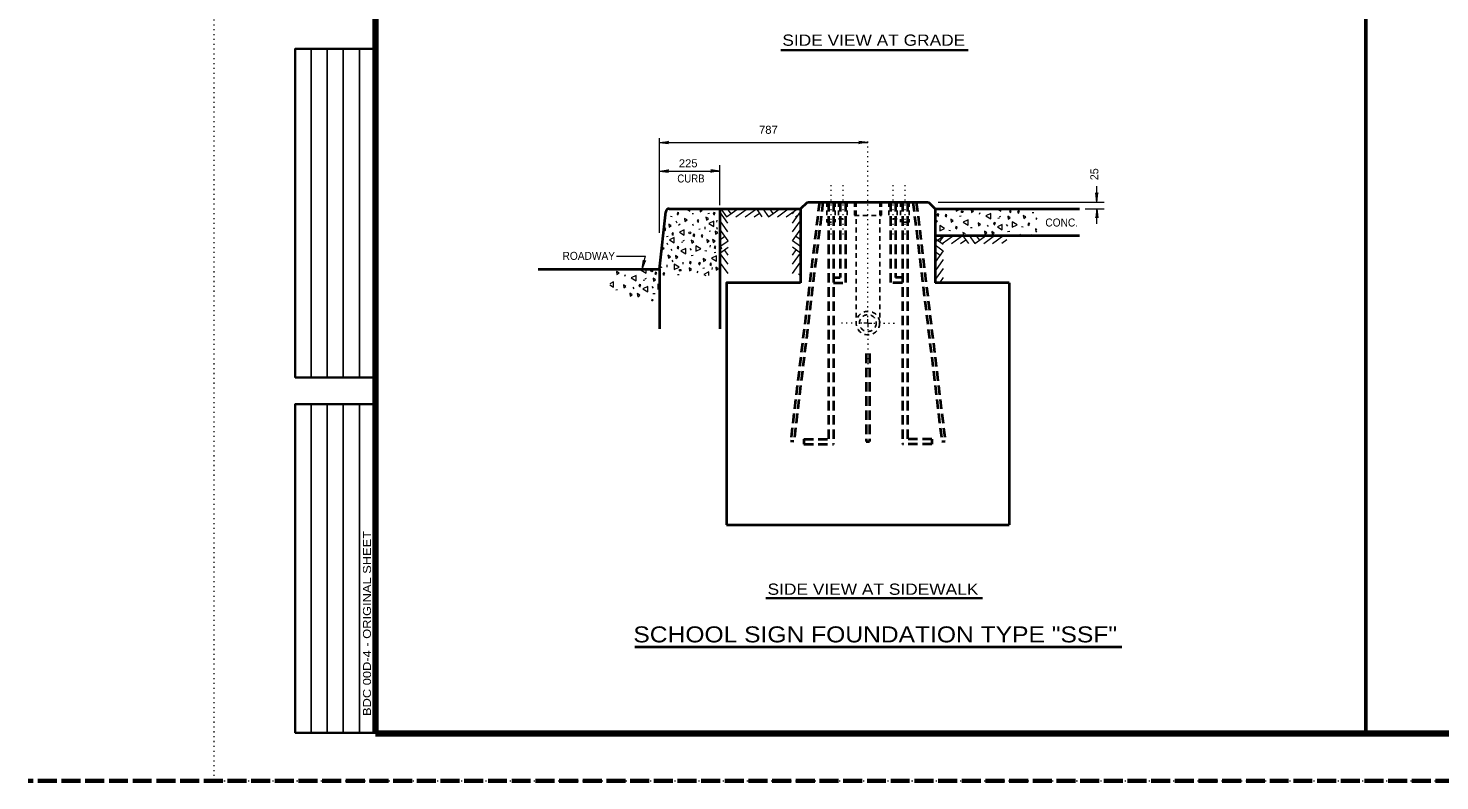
# Model space of a CAD drawing. Extents: x 312583 to 312854, y 144419 to 144597.
# Drawn here: x 312583.5 to 312717.6, y 144418.6 to 144490.1 of the extents above; entities that cross this region are included whole.
import ezdxf
from ezdxf.enums import TextEntityAlignment as Align

# ---------------------------------------------------------------- set-up
doc = ezdxf.new("R2010")
doc.units = 0
doc.header["$LTSCALE"] = 0.3
for name, pattern in [('DOTTED', [1.5, 0.3, -1.2]), ('LONG_DASHED', [7.5, 6, -1.5]), ('MEDIUM_DASHED', [4.5, 3, -1.5]), ('SHORT_DASHED', [2.7, 1.5, -1.2])]:
    doc.linetypes.add(name, pattern=pattern)
for name, color, linetype, lineweight in [('1', 7, 'Continuous', 40), ('2', 7, 'Continuous', 13), ('62', 7, 'DOTTED', 13), ('63', 7, 'LONG_DASHED', 60)]:
    doc.layers.add(name, color=color, linetype=linetype, lineweight=lineweight)

msp = doc.modelspace()

# ---------------------------------------------------------------- linework, layer by layer
at = {"layer": '1', "lineweight": 53}
msp.add_line((312710.5662, 144423.0846), (312710.5662, 144585.0846), dxfattribs=at)
at = {"layer": '1', "lineweight": 25}
for p, q in [((312610.4087, 144456.901), (312610.4087, 144488.1192)), ((312611.9315, 144456.901), (312611.9315, 144488.1192)), ((312613.4543, 144456.901), (312613.4543, 144488.1192)), ((312614.9772, 144456.901), (312614.9772, 144488.1192)), ((312610.4087, 144423.1446), (312610.4087, 144454.3629)), ((312611.9315, 144423.1446), (312611.9315, 144454.3629)), ((312613.4543, 144423.1446), (312613.4543, 144454.3629)), ((312614.9772, 144423.1446), (312614.9772, 144454.3629))]:
    msp.add_line(p, q, dxfattribs=at)
at = {"layer": '1', "linetype": 'DOTTED', "lineweight": 13}
for p, q in [((312659.772, 144475.1823), (312659.772, 144470.383)), ((312660.9066, 144475.1823), (312660.9066, 144470.383)), ((312665.66, 144475.1823), (312665.66, 144470.383)), ((312666.7946, 144475.1823), (312666.7946, 144470.383))]:
    msp.add_line(p, q, dxfattribs=at)
at = {"layer": '1'}
for p, q in [((312644.4003, 144472.9283), (312656.897, 144472.9283)), ((312649.2303, 144472.9283), (312649.2303, 144461.5127)), ((312656.897, 144472.9283), (312657.5333, 144473.5647)), ((312656.897, 144472.9283), (312656.897, 144465.898)), ((312657.5333, 144473.5647), (312669.0333, 144473.5647)), ((312669.0333, 144473.5647), (312669.6696, 144472.9283)), ((312669.6696, 144472.9283), (312669.6696, 144465.898)), ((312669.6696, 144472.9283), (312683.3853, 144472.9283)), ((312669.6696, 144470.3753), (312683.3853, 144470.3753)), ((312643.4803, 144467.1783), (312643.4803, 144461.5127)), ((312676.7, 144465.898), (312669.6696, 144465.898)), ((312676.7, 144465.898), (312676.7, 144442.898)), ((312649.8666, 144442.898), (312676.7, 144442.898))]:
    msp.add_line(p, q, dxfattribs=at)
at = {"layer": '1', "lineweight": 13}
for p, q in [((312645.9413, 144472.959), (312646.3553, 144472.706)), ((312646.3553, 144472.706), (312646.3553, 144472.959)), ((312649.9203, 144472.913), (312650.2576, 144472.453)), ((312650.549, 144472.913), (312650.6716, 144472.7443)), ((312650.733, 144472.1693), (312651.8063, 144472.9283)), ((312651.6146, 144472.1693), (312652.688, 144472.9283)), ((312652.688, 144472.9283), (312653.2246, 144472.1693)), ((312653.309, 144472.9283), (312653.8533, 144472.1693)), ((312653.8533, 144472.1693), (312654.942, 144472.936)), ((312653.9376, 144472.9283), (312654.2673, 144472.4607)), ((312654.5663, 144472.9283), (312654.689, 144472.7597)), ((312654.689, 144472.1693), (312655.724, 144472.9053)), ((312655.5323, 144472.1693), (312656.598, 144472.9283)), ((312656.1303, 144472.4453), (312656.4753, 144472.9283)), ((312670.398, 144472.9053), (312670.5436, 144472.9437)), ((312670.973, 144472.959), (312670.9806, 144472.9283)), ((312675.4656, 144472.959), (312675.9026, 144472.6983)), ((312675.9026, 144472.6983), (312675.9026, 144472.959)), ((312644.5306, 144472.2307), (312644.6993, 144472.1847)), ((312645.052, 144471.7707), (312645.1363, 144471.602)), ((312645.466, 144471.4563), (312645.282, 144471.326)), ((312646.5776, 144472.476), (312646.7233, 144472.4837)), ((312646.616, 144471.4947), (312646.7003, 144471.326)), ((312648.088, 144472.4607), (312648.2336, 144472.4913)), ((312648.939, 144471.6403), (312648.962, 144471.832)), ((312649.9893, 144471.5637), (312649.2303, 144472.6293)), ((312649.9893, 144470.7203), (312649.2533, 144471.763)), ((312652.4963, 144472.1693), (312652.9793, 144472.5143)), ((312656.1303, 144471.5637), (312656.897, 144472.6293)), ((312656.1303, 144470.7203), (312656.874, 144471.763)), ((312656.4063, 144472.1693), (312656.897, 144472.5143)), ((312672.0003, 144472.2307), (312672.146, 144472.2383)), ((312673.9093, 144472.5527), (312673.8403, 144472.384)), ((312675.6266, 144472.0237), (312675.7723, 144472.0543)), ((312675.7953, 144472.154), (312675.9256, 144472.223)), ((312678.8926, 144472.5757), (312679.0383, 144472.5833)), ((312644.1626, 144470.291), (312644.3083, 144470.3217)), ((312647.2216, 144470.9733), (312647.3673, 144471.0117)), ((312647.7813, 144471.2033), (312647.8043, 144470.9963)), ((312648.1953, 144470.7893), (312648.341, 144470.82)), ((312648.893, 144471.1727), (312648.9773, 144470.9963)), ((312649.997, 144469.8923), (312649.215, 144470.9733)), ((312649.2303, 144470.5977), (312649.399, 144470.7203)), ((312649.2303, 144469.9767), (312649.698, 144470.3063)), ((312656.1303, 144469.8923), (312656.9046, 144470.9733)), ((312656.8893, 144469.9767), (312656.4216, 144470.3063)), ((312656.8893, 144470.5977), (312656.7206, 144470.7203)), ((312669.6696, 144469.7697), (312670.5206, 144470.3753)), ((312669.6696, 144470.1453), (312669.8536, 144469.9)), ((312669.6696, 144470.107), (312670.4363, 144469.5703)), ((312670.4363, 144470.2987), (312670.0913, 144469.8157)), ((312670.145, 144470.36), (312670.2676, 144470.199)), ((312670.3366, 144469.6163), (312671.4023, 144470.383)), ((312670.973, 144470.889), (312671.1416, 144470.8507)), ((312671.2183, 144469.6163), (312672.2763, 144470.3907)), ((312672.2763, 144470.3907), (312672.8283, 144469.6317)), ((312672.905, 144470.3907), (312673.457, 144469.6317)), ((312673.02, 144471.1343), (312673.1733, 144471.142)), ((312673.457, 144469.6317), (312674.538, 144470.4137)), ((312673.5336, 144470.3983), (312673.871, 144469.9307)), ((312674.1623, 144470.3983), (312674.285, 144470.2297)), ((312674.285, 144469.6393), (312675.32, 144470.383)), ((312674.6223, 144471.3643), (312674.722, 144471.2263)), ((312675.1283, 144469.6393), (312676.194, 144470.4137)), ((312676.4316, 144471.4257), (312676.5543, 144471.2723)), ((312676.5466, 144470.774), (312676.7613, 144470.7817)), ((312677.8653, 144471.234), (312678.034, 144471.1957)), ((312678.8006, 144470.4597), (312678.7163, 144470.406)), ((312679.2453, 144470.728), (312679.3373, 144470.7893)), ((312644.1703, 144469.6853), (312644.2623, 144469.5167)), ((312644.5613, 144469.0873), (312644.661, 144468.9493)), ((312645.5656, 144469.7467), (312645.7113, 144469.7773)), ((312645.7343, 144469.877), (312645.8646, 144469.946)), ((312646.3706, 144469.1487), (312646.4933, 144468.9877)), ((312647.8043, 144468.957), (312647.973, 144468.9187)), ((312648.3103, 144469.2867), (312648.3333, 144469.4707)), ((312648.6936, 144468.7577), (312648.8393, 144468.7883)), ((312649.2303, 144469.348), (312649.997, 144469.8923)), ((312649.2303, 144468.7193), (312649.997, 144469.2637)), ((312649.997, 144468.5277), (312649.652, 144469.0183)), ((312656.8893, 144468.7193), (312656.1226, 144469.2637)), ((312656.1226, 144468.5277), (312656.4753, 144469.0183)), ((312656.8893, 144469.348), (312656.1303, 144469.8923)), ((312670.4363, 144468.9417), (312669.662, 144467.853)), ((312669.6696, 144469.486), (312670.4363, 144468.9417)), ((312669.6696, 144468.8573), (312670.1373, 144468.52)), ((312672.0923, 144469.624), (312672.583, 144469.9767)), ((312676.01, 144469.647), (312676.493, 144469.9997)), ((312644.1703, 144467.5923), (312644.1933, 144467.3777)), ((312644.6686, 144468.037), (312644.753, 144467.8683)), ((312645.7266, 144467.6613), (312645.7496, 144467.853)), ((312646.4856, 144468.497), (312646.7003, 144468.5047)), ((312649.997, 144467.6537), (312649.2303, 144468.7193)), ((312649.997, 144466.772), (312649.2303, 144467.8377)), ((312656.1226, 144467.6537), (312656.8893, 144468.7193)), ((312656.1226, 144466.772), (312656.8816, 144467.8377)), ((312669.6696, 144468.2287), (312669.8383, 144468.106)), ((312670.4363, 144468.106), (312669.6926, 144467.071)), ((312640.2373, 144466.657), (312640.1606, 144466.4883)), ((312641.947, 144466.128), (312642.0926, 144466.1587)), ((312642.1156, 144466.2583), (312642.246, 144466.335)), ((312642.223, 144466.8027), (312642.223, 144467.209)), ((312643.603, 144467.3547), (312643.7486, 144467.393)), ((312645.213, 144466.68), (312645.3586, 144466.6877)), ((312647.122, 144467.002), (312647.0453, 144466.8333)), ((312647.6203, 144467.278), (312647.766, 144467.301)), ((312648.502, 144467.14), (312648.525, 144467.3317)), ((312656.874, 144466.588), (312656.7053, 144466.703)), ((312670.4363, 144467.2627), (312669.6696, 144466.197)), ((312670.4363, 144466.3887), (312670.0913, 144465.898)), ((312638.7653, 144465.691), (312639.1256, 144465.4763)), ((312639.3403, 144465.2387), (312639.4936, 144465.254)), ((312640.9426, 144465.4763), (312641.05, 144465.3307)), ((312642.752, 144465.53), (312642.8746, 144465.3767)), ((312642.867, 144464.8783), (312643.0816, 144464.886)), ((312643.3346, 144465.783), (312643.3193, 144465.7907)), ((312642.8363, 144464.1577), (312642.8363, 144464.1807))]:
    msp.add_line(p, q, dxfattribs=at)
at = {"layer": '1', "linetype": 'MEDIUM_DASHED'}
for p, q in [((312658.6833, 144473.5647), (312655.9386, 144450.8483)), ((312659.0053, 144473.5647), (312656.253, 144450.81)), ((312659.5266, 144473.5647), (312659.5266, 144451.0477)), ((312660.0096, 144473.5647), (312660.0096, 144450.5647)), ((312660.6613, 144473.5647), (312660.6613, 144466.381)), ((312661.1443, 144473.5647), (312661.1443, 144465.898)), ((312665.4223, 144473.5647), (312665.4223, 144465.898)), ((312665.9053, 144473.5647), (312665.9053, 144466.381)), ((312666.557, 144473.5647), (312666.557, 144450.5647)), ((312667.04, 144473.5647), (312667.04, 144451.0477)), ((312667.5613, 144473.5647), (312670.3136, 144450.81)), ((312667.8833, 144473.5647), (312670.628, 144450.8483)), ((312660.0096, 144466.381), (312660.6613, 144466.381)), ((312666.557, 144466.381), (312665.9053, 144466.381)), ((312660.0096, 144465.898), (312661.1443, 144465.898)), ((312666.557, 144465.898), (312665.4223, 144465.898)), ((312663.1223, 144459.1667), (312663.1223, 144450.81)), ((312663.4443, 144459.1667), (312663.4443, 144450.81)), ((312656.253, 144450.81), (312655.9386, 144450.8483)), ((312657.2113, 144451.0477), (312659.5266, 144451.0477)), ((312657.2113, 144451.0477), (312657.2113, 144450.5647)), ((312657.2113, 144450.5647), (312660.002, 144450.5647)), ((312663.1223, 144450.81), (312663.4443, 144450.81)), ((312669.3553, 144450.5647), (312666.5646, 144450.5647)), ((312669.3553, 144451.0477), (312667.04, 144451.0477)), ((312669.3553, 144451.0477), (312669.3553, 144450.5647)), ((312670.3136, 144450.81), (312670.628, 144450.8483))]:
    msp.add_line(p, q, dxfattribs=at)
at = {"layer": '1', "linetype": 'SHORT_DASHED', "lineweight": 25}
for p, q in [((312659.3733, 144473.5647), (312659.3733, 144471.648)), ((312660.1706, 144473.5647), (312660.1706, 144471.648)), ((312660.5003, 144473.5647), (312660.5003, 144471.97)), ((312661.3053, 144473.5647), (312661.3053, 144471.97)), ((312662.164, 144473.5647), (312662.164, 144462.0647)), ((312664.4026, 144473.5647), (312664.4026, 144462.0647)), ((312664.5636, 144473.5647), (312664.5636, 144472.292)), ((312665.2613, 144473.5647), (312665.2613, 144471.97)), ((312666.0586, 144473.5647), (312666.0586, 144471.97)), ((312666.396, 144473.5647), (312666.396, 144471.648)), ((312667.1933, 144473.5647), (312667.1933, 144471.648)), ((312659.3733, 144471.648), (312660.1706, 144471.648)), ((312660.5003, 144471.97), (312661.3053, 144471.97)), ((312666.0586, 144471.97), (312665.2613, 144471.97)), ((312667.1933, 144471.648), (312666.396, 144471.648))]:
    msp.add_line(p, q, dxfattribs=at)
at = {"layer": '1', "lineweight": 158}
msp.add_line((312616.5, 144423.0846), (312849, 144423.0846), dxfattribs=at)
msp.add_lwpolyline([(312616.5, 144423.1446), (312616.5, 144585.0846), (312849, 144585.0846)], dxfattribs=at)
at = {"layer": '1', "lineweight": 35}
for points in [[(312616.5, 144456.901), (312608.8858, 144456.901), (312608.8858, 144488.1192), (312616.5, 144488.1192)], [(312616.5, 144423.1446), (312608.8858, 144423.1446), (312608.8858, 144454.3629), (312616.5, 144454.3629)]]:
    msp.add_lwpolyline(points, dxfattribs=at)
at = {"layer": '1', "lineweight": 13}
for points in [[(312647.352, 144472.6447), (312647.5436, 144472.7903), (312647.3136, 144472.9283)], [(312673.1273, 144472.568), (312673.3266, 144472.7137), (312673.089, 144472.8517)], [(312644.408, 144471.1803), (312644.6073, 144471.326), (312644.3696, 144471.464)], [(312645.2743, 144472.453), (312645.3203, 144472.5297), (312645.2053, 144472.568), (312645.1516, 144472.4147), (312645.2743, 144472.3457)], [(312645.9106, 144471.717), (312646.11, 144471.8703), (312645.8723, 144472.0083)], [(312647.1833, 144471.763), (312647.2293, 144471.8397), (312647.1143, 144471.878), (312647.053, 144471.7247), (312647.1833, 144471.6557)], [(312647.95, 144471.8473), (312648.1416, 144471.993), (312647.904, 144472.1387)], [(312648.6476, 144471.234), (312648.6476, 144471.7477), (312648.18, 144471.51)], [(312648.7166, 144472.4453), (312648.7703, 144472.5297), (312648.6476, 144472.568), (312648.594, 144472.4147), (312648.7166, 144472.3457)], [(312669.9763, 144472.3227), (312670.0223, 144472.3993), (312669.9073, 144472.4377), (312669.846, 144472.2843), (312669.9763, 144472.2153)], [(312670.7353, 144472.269), (312670.789, 144472.3533), (312670.6663, 144472.384), (312670.6126, 144472.2307), (312670.7353, 144472.1617)], [(312671.1953, 144471.6633), (312671.387, 144471.809), (312671.157, 144471.947)], [(312672.8053, 144471.3643), (312672.8053, 144471.8857), (312672.3376, 144471.648)], [(312673.7943, 144471.303), (312673.986, 144471.4487), (312673.756, 144471.5867)], [(312674.952, 144471.9623), (312674.952, 144472.476), (312674.4843, 144472.246)], [(312675.343, 144471.4947), (312675.389, 144471.579), (312675.274, 144471.6173), (312675.2126, 144471.464), (312675.343, 144471.395)], [(312676.608, 144471.9317), (312676.7996, 144472.0773), (312676.562, 144472.2153)], [(312676.861, 144472.6677), (312676.907, 144472.7443), (312676.792, 144472.7827), (312676.7383, 144472.6293), (312676.861, 144472.5603)], [(312676.999, 144471.6863), (312676.999, 144471.1727), (312677.4666, 144471.4027)], [(312677.6276, 144472.614), (312677.6736, 144472.6907), (312677.5586, 144472.729), (312677.4973, 144472.5757), (312677.6276, 144472.5067)], [(312678.0876, 144472.0083), (312678.2793, 144472.154), (312678.0416, 144472.292)], [(312678.609, 144471.4563), (312678.655, 144471.5407), (312678.54, 144471.5713), (312678.4863, 144471.418), (312678.609, 144471.349)], [(312644.891, 144469.6853), (312644.891, 144470.199), (312644.4233, 144469.969)], [(312644.7836, 144470.5133), (312644.8296, 144470.5977), (312644.7146, 144470.636), (312644.6533, 144470.4827), (312644.7836, 144470.4137)], [(312645.834, 144470.4213), (312645.834, 144470.935), (312645.374, 144470.705)], [(312646.8, 144470.3907), (312646.846, 144470.4673), (312646.731, 144470.5057), (312646.6696, 144470.3523), (312646.8, 144470.2833)], [(312647.5666, 144470.337), (312647.6126, 144470.4137), (312647.4976, 144470.452), (312647.4363, 144470.2987), (312647.5666, 144470.2297)], [(312648.824, 144470.5133), (312649.0156, 144470.659), (312648.7856, 144470.797)], [(312670.1066, 144471.3413), (312670.1066, 144470.8277), (312670.5743, 144471.0577)], [(312671.7243, 144471.1113), (312671.7703, 144471.1957), (312671.6476, 144471.2263), (312671.594, 144471.073), (312671.7243, 144471.004)], [(312674.3923, 144470.5057), (312674.584, 144470.6513), (312674.354, 144470.797)], [(312675.0976, 144470.4673), (312675.2893, 144470.613), (312675.0593, 144470.751)], [(312676.0483, 144470.9273), (312676.0483, 144471.441), (312675.5806, 144471.211)], [(312645.282, 144469.2177), (312645.328, 144469.302), (312645.213, 144469.3403), (312645.1516, 144469.187), (312645.282, 144469.1103)], [(312645.9873, 144468.6503), (312645.9873, 144469.164), (312645.5196, 144468.934)], [(312646.547, 144469.6547), (312646.7386, 144469.8003), (312646.501, 144469.9383)], [(312646.938, 144469.4093), (312646.938, 144468.8957), (312647.4056, 144469.1257)], [(312648.0266, 144469.7313), (312648.2183, 144469.877), (312647.9806, 144470.015)], [(312648.5786, 144469.716), (312648.7703, 144469.8617), (312648.5326, 144469.9997)], [(312648.801, 144469.2637), (312648.847, 144469.348), (312648.732, 144469.3787), (312648.6706, 144469.233), (312648.801, 144469.1563)], [(312644.3313, 144468.2287), (312644.523, 144468.3743), (312644.293, 144468.52)], [(312644.8756, 144467.669), (312644.8756, 144467.1477), (312645.3433, 144467.3853)], [(312645.0366, 144468.1903), (312645.2283, 144468.336), (312644.9983, 144468.474)], [(312646.455, 144467.7993), (312646.501, 144467.8837), (312646.386, 144467.9143), (312646.3246, 144467.761), (312646.455, 144467.692)], [(312647.329, 144467.6997), (312647.375, 144467.784), (312647.26, 144467.8147), (312647.1986, 144467.669), (312647.329, 144467.5923)], [(312647.6816, 144467.9067), (312647.881, 144468.0523), (312647.6433, 144468.1903)], [(312648.387, 144467.646), (312648.4406, 144467.7303), (312648.318, 144467.761), (312648.2643, 144467.6077), (312648.387, 144467.5387)], [(312648.893, 144467.9373), (312648.893, 144468.451), (312648.4253, 144468.221)], [(312639.4476, 144466.6723), (312639.647, 144466.818), (312639.4093, 144466.956)], [(312641.2723, 144466.0667), (312641.2723, 144466.588), (312640.8046, 144466.3503)], [(312642.9283, 144466.036), (312643.12, 144466.1817), (312642.89, 144466.3197)], [(312643.1813, 144466.772), (312643.2273, 144466.8487), (312643.1123, 144466.887), (312643.0586, 144466.7337), (312643.1813, 144466.6647)], [(312643.948, 144466.7183), (312643.994, 144466.8027), (312643.879, 144466.8333), (312643.8176, 144466.68), (312643.948, 144466.611)], [(312646.34, 144467.0173), (312646.5316, 144467.163), (312646.3016, 144467.301)], [(312648.8776, 144467.0787), (312649.0693, 144467.232), (312648.8393, 144467.37)], [(312640.1146, 144465.4073), (312640.3063, 144465.553), (312640.0763, 144465.6987)], [(312640.7126, 144464.6177), (312640.9043, 144464.7633), (312640.6743, 144464.9013)], [(312641.418, 144464.5717), (312641.6096, 144464.7173), (312641.3796, 144464.863)], [(312641.6633, 144465.599), (312641.7093, 144465.6833), (312641.5943, 144465.7217), (312641.5406, 144465.5683), (312641.6633, 144465.4993)], [(312642.3686, 144465.0317), (312642.3686, 144465.553), (312641.901, 144465.3153)]]:
    msp.add_lwpolyline(points, close=True, dxfattribs=at)
for points in [[(312649.33, 144472.913), (312649.8666, 144472.1693), (312650.9246, 144472.9283)], [(312671.6706, 144472.959), (312671.6706, 144472.6983), (312672.1383, 144472.936), (312672.0923, 144472.959)], [(312669.754, 144471.6097), (312669.9073, 144471.7323), (312669.754, 144471.8243)], [(312679.3373, 144472.0467), (312679.2223, 144471.993), (312679.3373, 144471.924)], [(312643.971, 144470.912), (312644.0553, 144470.866), (312644.0553, 144470.9733)], [(312644.0553, 144470.9733), (312644.1013, 144471.0577), (312643.9863, 144471.0883)], [(312672.5523, 144470.5287), (312672.3146, 144470.6667), (312672.353, 144470.406)], [(312677.8116, 144470.406), (312677.7043, 144470.4673), (312677.712, 144470.406)], [(312679.3373, 144470.935), (312679.207, 144471.0117), (312679.2453, 144470.728)], [(312643.764, 144469.049), (312643.925, 144469.1717), (312643.787, 144469.256)], [(312649.307, 144469.2943), (312649.3683, 144469.141), (312649.2456, 144469.072)], [(312642.0006, 144467.209), (312641.7553, 144467.0863), (312642.223, 144466.8027)], [(312648.1646, 144466.5727), (312648.1646, 144466.9253), (312647.697, 144466.6953), (312647.904, 144466.5727)], [(312639.1256, 144465.4763), (312639.1256, 144465.99), (312638.7653, 144465.806)], [(312643.3193, 144465.7907), (312643.3193, 144465.277), (312643.396, 144465.3153)], [(312642.8363, 144464.1807), (312642.89, 144464.265), (312642.7673, 144464.3033), (312642.7213, 144464.1807)]]:
    msp.add_lwpolyline(points, dxfattribs=at)
at = {"layer": '1', "linetype": 'SHORT_DASHED', "lineweight": 25}
msp.add_lwpolyline([(312662.003, 144473.5647), (312662.003, 144472.292), (312664.5636, 144472.292)], dxfattribs=at)
at = {"layer": '1'}
for points in [[(312631.965, 144467.1783), (312643.4803, 144467.1783), (312644.086, 144472.637)], [(312656.897, 144465.898), (312649.8666, 144465.898), (312649.8666, 144442.898)]]:
    msp.add_lwpolyline(points, dxfattribs=at)
at = {"layer": '1', "lineweight": 13}
for centre, radius in [((312672.2411, 144472.6358), 0.0784), ((312646.3692, 144470.6327), 0.0865), ((312642.7519, 144467.0154), 0.0865), ((312645.4516, 144467.0859), 0.0784)]:
    msp.add_circle(centre, radius, dxfattribs=at)
at = {"layer": '1', "linetype": 'SHORT_DASHED', "lineweight": 25}
for radius in [1.1181, 0.7986]:
    msp.add_circle((312663.2827, 144462.0666), radius, dxfattribs=at)
at = {"layer": '1'}
msp.add_arc((312644.3984, 144472.6082), 0.3194, 90, 175.30452, dxfattribs=at)
at = {"layer": '2', "lineweight": 35}
for p, q in [((312655.023, 144488.001), (312672.819, 144488.001)), ((312653.5868, 144435.929), (312674.1853, 144435.929))]:
    msp.add_line(p, q, dxfattribs=at)
at = {"layer": '2'}
for p, q in [((312643.4803, 144470.6283), (312643.4803, 144479.629)), ((312643.4803, 144479.2227), (312644.3466, 144479.33)), ((312643.4803, 144479.2227), (312663.2833, 144479.2227)), ((312643.4803, 144479.2227), (312644.3466, 144479.1153)), ((312644.3466, 144479.33), (312644.0706, 144479.2227)), ((312644.3466, 144479.1153), (312644.0706, 144479.2227)), ((312662.417, 144479.33), (312662.693, 144479.2227)), ((312663.2833, 144479.2227), (312662.417, 144479.33)), ((312662.417, 144479.1153), (312662.693, 144479.2227)), ((312663.2833, 144479.2227), (312662.417, 144479.1153)), ((312649.2303, 144473.258), (312649.2303, 144477.0607)), ((312643.4803, 144476.501), (312644.3466, 144476.6083)), ((312643.4803, 144476.501), (312644.3466, 144476.3937)), ((312643.4803, 144476.501), (312649.2303, 144476.501)), ((312644.3466, 144476.6083), (312644.0706, 144476.501)), ((312644.3466, 144476.3937), (312644.0706, 144476.501)), ((312648.364, 144476.6083), (312648.64, 144476.501)), ((312649.2303, 144476.501), (312648.364, 144476.6083)), ((312648.364, 144476.3937), (312648.64, 144476.501)), ((312649.2303, 144476.501), (312648.364, 144476.3937)), ((312684.9263, 144474.431), (312685.0336, 144474.155)), ((312685.0336, 144473.5647), (312684.9263, 144474.431)), ((312685.0336, 144473.5647), (312685.0336, 144475.0827)), ((312685.141, 144474.431), (312685.0336, 144474.155)), ((312685.0336, 144473.5647), (312685.141, 144474.431)), ((312669.9533, 144473.5647), (312685.716, 144473.5647)), ((312683.922, 144472.9283), (312685.716, 144472.9283)), ((312685.0336, 144472.9283), (312684.9263, 144472.062)), ((312685.0336, 144471.4947), (312685.0336, 144472.9283)), ((312685.0336, 144472.9283), (312685.141, 144472.062)), ((312684.9263, 144472.062), (312685.0336, 144472.338)), ((312685.141, 144472.062), (312685.0336, 144472.338)), ((312639.4093, 144468.4203), (312642.154, 144468.4203)), ((312641.855, 144467.1783), (312642.154, 144468.4203)), ((312641.855, 144467.1783), (312641.9546, 144468.0447)), ((312641.855, 144467.1783), (312642.1616, 144467.9987)), ((312641.9546, 144468.0447), (312641.993, 144467.7533)), ((312642.1616, 144467.9987), (312641.993, 144467.7533)), ((312663.2833, 144462.0647), (312662.9, 144462.0647)), ((312663.2833, 144462.0647), (312663.2833, 144462.448)), ((312663.2833, 144462.0647), (312663.6666, 144462.0647)), ((312663.2833, 144462.0647), (312663.2833, 144461.6813))]:
    msp.add_line(p, q, dxfattribs=at)
at = {"layer": '2', "linetype": 'DOTTED'}
for p, q in [((312663.2833, 144462.6397), (312663.2833, 144479.629)), ((312662.7083, 144462.0647), (312660.462, 144462.0647)), ((312663.8583, 144462.0647), (312665.913, 144462.0647)), ((312663.2833, 144461.4897), (312663.2833, 144457.6563))]:
    msp.add_line(p, q, dxfattribs=at)
at = {"layer": '2', "lineweight": 40}
msp.add_line((312641.1593, 144431.2983), (312687.401, 144431.2983), dxfattribs=at)
at = {"layer": '62'}
msp.add_line((312601.2, 144418.5846), (312601.2, 144596.7846), dxfattribs=at)
msp.add_lwpolyline([(312601.2, 144418.5846), (312853.5, 144418.5846), (312853.5, 144596.7846)], dxfattribs=at)
at = {"layer": '63'}
msp.add_line((312851.75, 144418.5846), (312583.526, 144418.5846), dxfattribs=at)

# ---------------------------------------------------------------- texts
at = {"layer": '1', "width": 1.2}
msp.add_text('BDC 00D-4 - ORIGINAL SHEET', height=0.7614, rotation=90, dxfattribs=at).set_placement((312616.0832, 144424.7374))
at = {"layer": '2', "width": 1.15}
for s, height, p in [('SIDE VIEW AT GRADE', 1.07, (312663.8449, 144488.4086)), ('SIDE VIEW AT SIDEWALK', 1.07, (312663.7644, 144436.2508)), ('SCHOOL SIGN FOUNDATION TYPE "SSF"', 1.52, (312663.9806, 144431.7314))]:
    msp.add_text(s, height=height, dxfattribs=at).set_placement(p, align=Align.CENTER)
at = {"layer": '2'}
for s, width, p in [('787', 1.05, (312652.9422, 144480.0453)), ('225', 1.05, (312645.3248, 144476.8654)), ('CURB', 0.9, (312645.1822, 144475.4214)), ('CONC.', 0.95, (312680.1388, 144471.24)), ('ROADWAY', 0.95, (312634.2774, 144468.0725))]:
    msp.add_text(s, height=0.76, dxfattribs=dict(at, width=width)).set_placement(p)
msp.add_text('25', height=0.76, rotation=90, dxfattribs=at).set_placement((312685.1718, 144475.6397))

doc.saveas('drawing.dxf')
